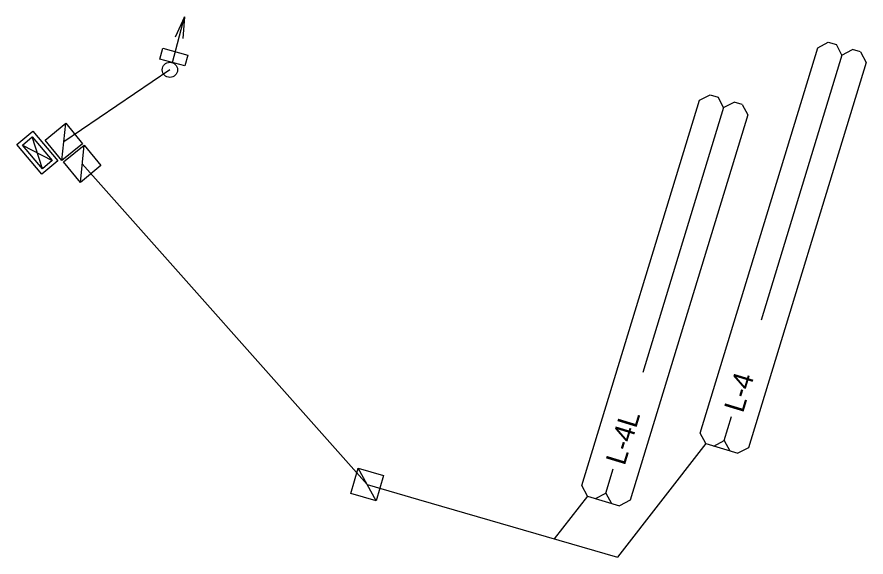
# Model space of a CAD drawing. Extents: x 925680 to 926006, y 853415 to 857998.
# Drawn here: x 925781.9 to 925882, y 857934.4 to 857998.1 of the extents above; entities that cross this region are included whole.
import ezdxf

# ---------------------------------------------------------------- set-up
doc = ezdxf.new("R2010")
doc.units = 0
for name, color, linetype in [('ConduitOT', 7, 'Continuous'), ('ControllerB_ep', 7, 'Continuous'), ('LoopLI', 7, 'Continuous'), ('Loops', 7, 'Continuous'), ('Pedestal', 7, 'Continuous'), ('PedHead', 7, 'Continuous'), ('PullBox', 7, 'Continuous')]:
    doc.layers.add(name, color=color, linetype=linetype)

msp = doc.modelspace()

# ---------------------------------------------------------------- linework, layer by layer
at = {"layer": 'ConduitOT'}
for p, q in [((925799.95, 857991.88), (925787.45, 857983.38)), ((925823.2, 857942.98), (925829.27, 857941.22))]:
    msp.add_line(p, q, dxfattribs=at)
msp.add_lwpolyline([(925823.2, 857942.98), (925789.61, 857980.8)], dxfattribs=at)
at = {"layer": 'ControllerB_ep'}
for p, q in [((925781.92, 857983.07), (925783.78, 857984.64)), ((925783.78, 857984.64), (925786.73, 857981.15)), ((925782.57, 857983.01), (925783.73, 857983.99)), ((925784.92, 857980.22), (925783.73, 857983.99)), ((925783.73, 857983.99), (925786.08, 857981.2)), ((925784.87, 857979.58), (925781.92, 857983.07)), ((925782.57, 857983.01), (925786.08, 857981.2)), ((925784.92, 857980.22), (925782.57, 857983.01)), ((925786.73, 857981.15), (925784.87, 857979.58)), ((925786.08, 857981.2), (925784.92, 857980.22))]:
    msp.add_line(p, q, dxfattribs=at)
at = {"layer": 'LoopLI'}
for p, q in [((925863.13, 857947.8), (925852.71, 857934.42)), ((925829.27, 857941.22), (925852.71, 857934.42)), ((925849.18, 857941.61), (925845.27, 857936.58))]:
    msp.add_line(p, q, dxfattribs=at)
at = {"layer": 'Loops'}
for p, q in [((925862.47, 857949.04), (925876.35, 857994.49)), ((925876.35, 857994.49), (925877.58, 857995.15)), ((925877.58, 857995.15), (925878.53, 857994.86)), ((925879.19, 857993.62), (925878.53, 857994.86)), ((925879.19, 857993.62), (925880.42, 857994.28)), ((925881.37, 857993.99), (925880.42, 857994.28)), ((925879.19, 857993.62), (925869.65, 857962.37)), ((925881.37, 857993.99), (925882.03, 857992.75)), ((925882.03, 857992.75), (925868.16, 857947.3)), ((925848.53, 857942.84), (925862.4, 857988.29)), ((925862.4, 857988.29), (925863.64, 857988.95)), ((925863.64, 857988.95), (925864.58, 857988.66)), ((925865.24, 857987.42), (925864.58, 857988.66)), ((925865.24, 857987.42), (925855.7, 857956.18)), ((925865.24, 857987.42), (925866.48, 857988.08)), ((925867.42, 857987.79), (925866.48, 857988.08)), ((925867.42, 857987.79), (925868.08, 857986.56)), ((925868.08, 857986.56), (925854.21, 857941.11)), ((925865.32, 857948.17), (925866.18, 857951.01)), ((925863.13, 857947.8), (925862.47, 857949.04)), ((925863.13, 857947.8), (925866.92, 857946.65)), ((925864.08, 857947.51), (925865.32, 857948.17)), ((925865.32, 857948.17), (925865.97, 857946.93)), ((925868.16, 857947.3), (925866.92, 857946.65)), ((925851.37, 857941.97), (925852.23, 857944.81)), ((925849.18, 857941.61), (925848.53, 857942.84)), ((925849.18, 857941.61), (925852.97, 857940.45)), ((925850.13, 857941.32), (925851.37, 857941.97)), ((925851.37, 857941.97), (925852.03, 857940.74)), ((925854.21, 857941.11), (925852.97, 857940.45))]:
    msp.add_line(p, q, dxfattribs=at)
at = {"layer": 'Pedestal'}
msp.add_circle((925799.95, 857991.88), 0.9, dxfattribs=at)
at = {"layer": 'PedHead'}
for p, q in [((925800.24, 857992.74), (925801.69, 857998.12)), ((925801.69, 857998.12), (925800.57, 857995.72)), ((925801.69, 857998.12), (925801.46, 857995.56)), ((925798.76, 857993.13), (925799.11, 857994.43)), ((925799.11, 857994.43), (925802.06, 857993.63)), ((925802.06, 857993.63), (925801.71, 857992.34)), ((925801.71, 857992.34), (925798.76, 857993.13))]:
    msp.add_line(p, q, dxfattribs=at)
at = {"layer": 'PullBox'}
for p, q in [((925785.25, 857983.59), (925787.67, 857985.58)), ((925787.23, 857981.18), (925787.67, 857985.58)), ((925787.67, 857985.58), (925789.65, 857983.16)), ((925787.23, 857981.18), (925785.25, 857983.59)), ((925789.65, 857983.16), (925787.23, 857981.18)), ((925787.41, 857981.02), (925789.83, 857983)), ((925789.4, 857978.6), (925789.83, 857983)), ((925789.83, 857983), (925791.81, 857980.58)), ((925789.4, 857978.6), (925787.41, 857981.02)), ((925791.81, 857980.58), (925789.4, 857978.6)), ((925821.27, 857941.91), (925822.14, 857944.91)), ((925822.14, 857944.91), (925825.14, 857944.04)), ((925824.27, 857941.04), (925822.14, 857944.91)), ((925825.14, 857944.04), (925824.27, 857941.04)), ((925824.27, 857941.04), (925821.27, 857941.91))]:
    msp.add_line(p, q, dxfattribs=at)

# ---------------------------------------------------------------- texts
at = {"layer": 'Loops'}
for s, p in [('L-4  ', (925867.52, 857951.32)), ('L-4L ', (925853.57, 857945.12))]:
    msp.add_text(s, height=2.376, rotation=73.0261, dxfattribs=at).set_placement(p)

doc.saveas('drawing.dxf')
